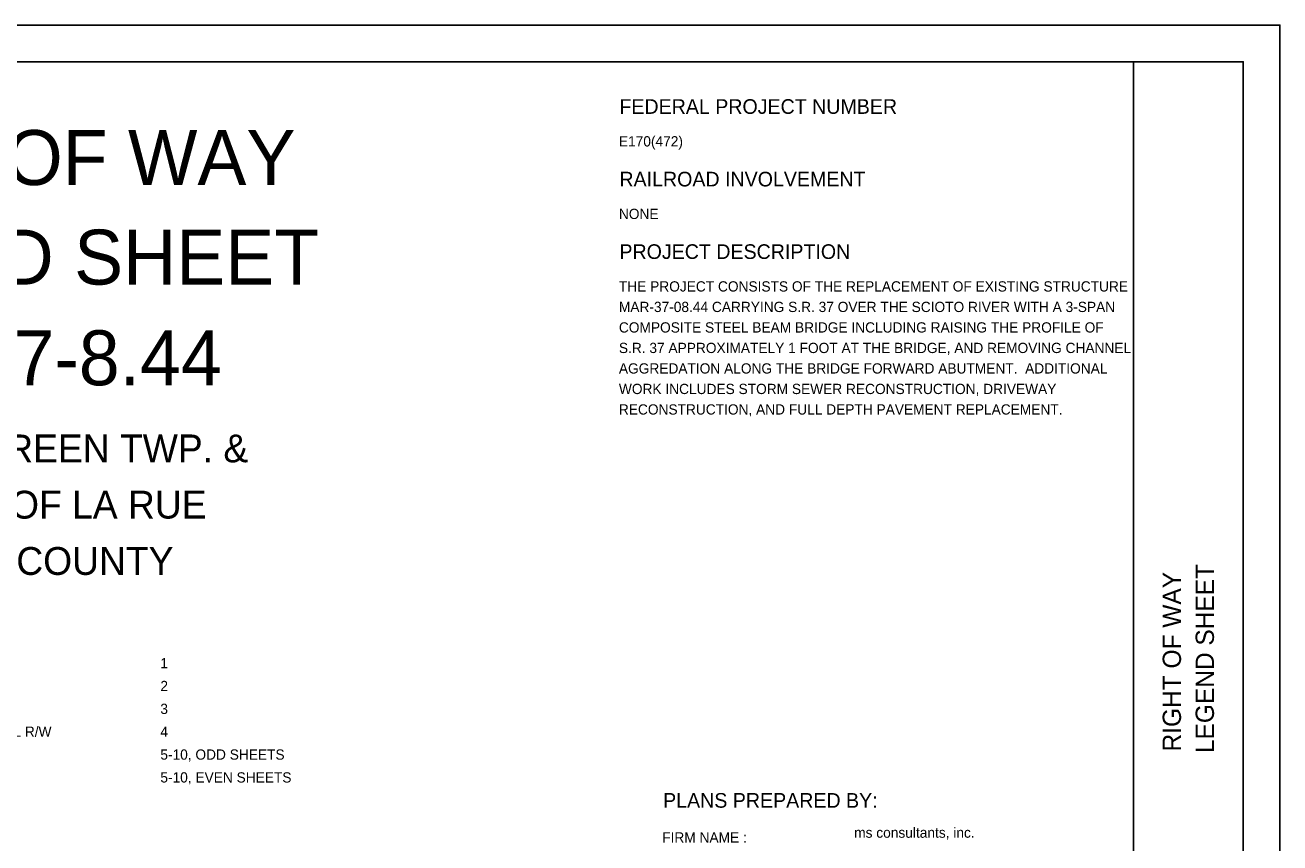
# Model space of a CAD drawing. Extents: x 0 to 59.1, y -2.4 to 22.
# Drawn here: x 16.87 to 34, y 10.83 to 22 of the extents above; entities that cross this region are included whole.
import ezdxf

# ---------------------------------------------------------------- set-up
doc = ezdxf.new("R2010")
doc.units = 0
for name, color, linetype in [('SH_Border', 7, 'Continuous'), ('SH_Cut_Line', 7, 'Continuous'), ('SH_Data', 7, 'Continuous'), ('SH_Text', 7, 'Continuous')]:
    doc.layers.add(name, color=color, linetype=linetype)

msp = doc.modelspace()

# ---------------------------------------------------------------- linework, layer by layer
at = {"layer": 'SH_Border'}
msp.add_line((32, 0.5), (32, 21.5), dxfattribs=at)
msp.add_lwpolyline([(1.5, 21.5), (33.5, 21.5), (33.5, 0.5), (1.5, 0.5)], close=True, dxfattribs=at)
at = {"layer": 'SH_Cut_Line'}
msp.add_lwpolyline([(0, 0), (34, 0), (34, 22), (0, 22)], close=True, dxfattribs=at)

# ---------------------------------------------------------------- texts
at = {"layer": 'SH_Data'}
for s, height, p in [('RIGHT OF WAY', 0.75, (13.21, 19.816)), ('LEGEND SHEET', 0.75, (13.141, 18.457)), ('MAR-37-8.44', 0.75, (13.596, 17.082)), ('BOWLING GREEN TWP. &', 0.38, (13.681, 16.03)), ('VILLAGE OF LA RUE', 0.38, (14.41, 15.262)), ('MARION COUNTY', 0.38, (14.581, 14.493)), ('1', 0.14, (18.721, 13.218)), ('2', 0.14, (18.721, 12.906)), ('3', 0.14, (18.721, 12.594)), ('SUMMARY OF ADDITIONAL R/W', 0.14, (14.375, 12.282)), ('4', 0.14, (18.721, 12.282)), ('5-10, ODD SHEETS', 0.14, (18.721, 11.97)), ('5-10, EVEN SHEETS', 0.14, (18.721, 11.658))]:
    msp.add_text(s, height=height, dxfattribs=at).set_placement(p)
for s, p in [('LEGEND SHEET', (33.1, 12.06)), ('RIGHT OF WAY', (32.65, 12.082))]:
    msp.add_text(s, height=0.25, rotation=90, dxfattribs=at).set_placement(p)
at = {"layer": 'SH_Text'}
for s, height, p in [('FEDERAL PROJECT NUMBER', 0.2, (24.986, 20.788)), ('E170(472)', 0.14, (24.979, 20.343)), ('RAILROAD INVOLVEMENT', 0.2, (24.986, 19.797)), ('NONE', 0.14, (24.979, 19.352)), ('PROJECT DESCRIPTION', 0.2, (24.986, 18.807)), ('THE PROJECT CONSISTS OF THE REPLACEMENT OF EXISTING STRUCTURE', 0.14, (24.979, 18.362)), ('MAR-37-08.44 CARRYING S.R. 37 OVER THE SCIOTO RIVER WITH A 3-SPAN', 0.14, (24.979, 18.082)), ('COMPOSITE STEEL BEAM BRIDGE INCLUDING RAISING THE PROFILE OF', 0.14, (24.979, 17.802)), ('S.R. 37 APPROXIMATELY 1 FOOT AT THE BRIDGE, AND REMOVING CHANNEL', 0.14, (24.979, 17.522)), ('AGGREDATION ALONG THE BRIDGE FORWARD ABUTMENT.  ADDITIONAL', 0.14, (24.979, 17.242)), ('WORK INCLUDES STORM SEWER RECONSTRUCTION, DRIVEWAY', 0.14, (24.979, 16.962)), ('RECONSTRUCTION, AND FULL DEPTH PAVEMENT REPLACEMENT.', 0.14, (24.979, 16.682)), ('PLANS PREPARED BY:', 0.2, (25.582, 11.314)), ('FIRM NAME :', 0.14, (25.57, 10.838)), ('ms consultants, inc.', 0.14, (28.19, 10.904))]:
    msp.add_text(s, height=height, dxfattribs=at).set_placement(p)

doc.saveas('drawing.dxf')
